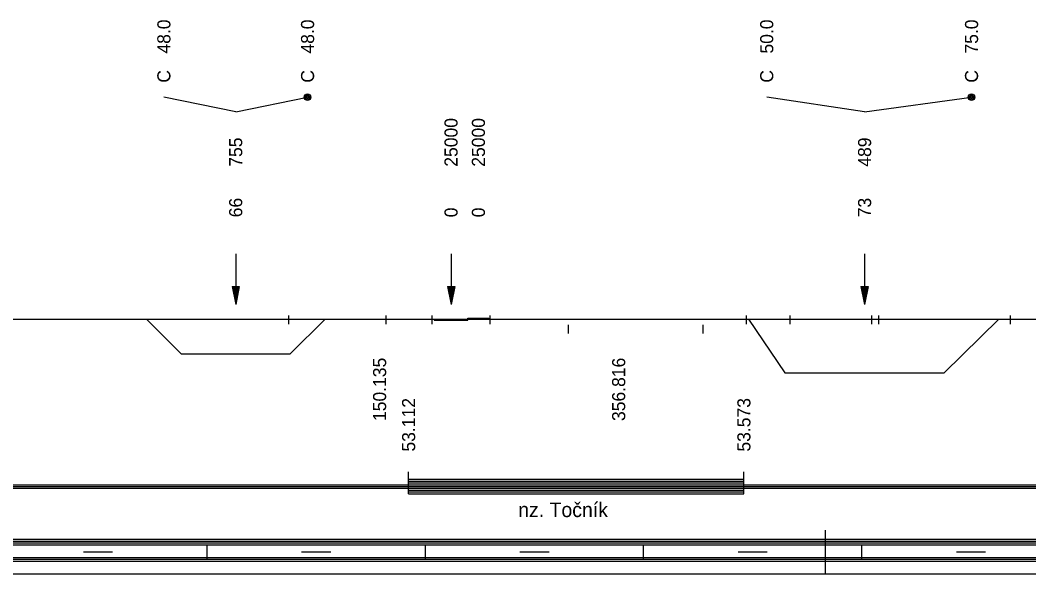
# Model space of a CAD drawing. Extents: x 2 to 10148, y 0 to 380.
# Drawn here: x 5559.3 to 5697.9, y 0 to 76.1 of the extents above; entities that cross this region are included whole.
import ezdxf

# ---------------------------------------------------------------- set-up
doc = ezdxf.new("R2010")
doc.units = 0
for name, color, linetype in [('KRIV1_CARA', 7, 'Continuous'), ('KRIV1_TEXT', 7, 'Continuous'), ('L_OBJEKTY_TEXT', 7, 'Continuous'), ('L_OBJEKTY_TVAR', 7, 'Continuous'), ('RAM', 7, 'Continuous'), ('STAN_CARA', 7, 'Continuous')]:
    doc.layers.add(name, color=color, linetype=linetype)

msp = doc.modelspace()

# ---------------------------------------------------------------- linework, layer by layer
for p, q in [((5596.19, 35.51), (5596.19, 34.32)), ((5609.58, 35.51), (5609.58, 34.32)), ((5615.9, 35.51), (5615.9, 34.32)), ((5623.88, 35.51), (5623.88, 34.32)), ((5659.08, 35.51), (5659.08, 34.32)), ((5665.09, 35.51), (5665.09, 34.32)), ((5676.33, 35.51), (5676.33, 34.32)), ((5677.27, 35.51), (5677.27, 34.32)), ((5695.36, 35.51), (5695.36, 34.32)), ((5634.63, 34.2), (5634.63, 33.01)), ((5653.13, 34.2), (5653.13, 33.01))]:
    msp.add_line(p, q)
at = {"layer": 'KRIV1_CARA'}
for p, q in [((5128.6, 35), (5974.91, 35)), ((5576.66, 35), (5581.46, 30.23)), ((5596.41, 30.23), (5601.21, 35)), ((5616.22, 35), (5616.22, 34.86)), ((5616.22, 34.86), (5620.85, 34.86)), ((5620.85, 35), (5620.85, 35.14)), ((5620.85, 35.14), (5623.73, 35.14)), ((5620.85, 34.86), (5620.85, 35)), ((5623.73, 35.14), (5623.73, 35)), ((5659.42, 35), (5664.42, 27.64)), ((5686.32, 27.64), (5693.82, 35)), ((5581.46, 30.23), (5596.41, 30.23)), ((5664.42, 27.64), (5686.32, 27.64))]:
    msp.add_line(p, q, dxfattribs=at)
at = {"layer": 'KRIV1_TEXT'}
for p, q in [((5588.93, 63.5), (5579.06, 65.5)), ((5588.93, 63.5), (5598.81, 65.5)), ((5675.37, 63.5), (5661.92, 65.5)), ((5675.37, 63.5), (5690.07, 65.5)), ((5588.93, 44), (5588.93, 42.2)), ((5618.53, 44), (5618.53, 42.2)), ((5675.37, 44), (5675.37, 42.2)), ((5588.93, 42.2), (5588.93, 40)), ((5618.53, 42.2), (5618.53, 40)), ((5675.37, 42.2), (5675.37, 40)), ((5588.43, 39.5), (5588.93, 37)), ((5588.43, 39.5), (5589.43, 39.5)), ((5588.53, 39.5), (5588.93, 37.5)), ((5588.63, 39.5), (5588.93, 38)), ((5588.73, 39.5), (5588.93, 38.5)), ((5588.83, 39.5), (5588.93, 39)), ((5588.93, 40), (5588.93, 37)), ((5589.43, 39.5), (5588.93, 37)), ((5589.33, 39.5), (5588.93, 37.5)), ((5589.23, 39.5), (5588.93, 38)), ((5589.13, 39.5), (5588.93, 38.5)), ((5589.03, 39.5), (5588.93, 39)), ((5588.93, 39.5), (5588.93, 39.5)), ((5588.93, 39.5), (5588.93, 39.5)), ((5618.03, 39.5), (5618.53, 37)), ((5618.03, 39.5), (5619.03, 39.5)), ((5618.13, 39.5), (5618.53, 37.5)), ((5618.23, 39.5), (5618.53, 38)), ((5618.33, 39.5), (5618.53, 38.5)), ((5618.43, 39.5), (5618.53, 39)), ((5618.53, 40), (5618.53, 37)), ((5619.03, 39.5), (5618.53, 37)), ((5618.93, 39.5), (5618.53, 37.5)), ((5618.83, 39.5), (5618.53, 38)), ((5618.73, 39.5), (5618.53, 38.5)), ((5618.63, 39.5), (5618.53, 39)), ((5618.53, 39.5), (5618.53, 39.5)), ((5618.53, 39.5), (5618.53, 39.5)), ((5674.87, 39.5), (5675.37, 37)), ((5674.87, 39.5), (5675.87, 39.5)), ((5674.97, 39.5), (5675.37, 37.5)), ((5675.07, 39.5), (5675.37, 38)), ((5675.17, 39.5), (5675.37, 38.5)), ((5675.27, 39.5), (5675.37, 39)), ((5675.37, 40), (5675.37, 37)), ((5675.87, 39.5), (5675.37, 37)), ((5675.77, 39.5), (5675.37, 37.5)), ((5675.67, 39.5), (5675.37, 38)), ((5675.57, 39.5), (5675.37, 38.5)), ((5675.47, 39.5), (5675.37, 39)), ((5675.37, 39.5), (5675.37, 39.5)), ((5675.37, 39.5), (5675.37, 39.5))]:
    msp.add_line(p, q, dxfattribs=at)
for centre, radius in [((5598.81, 65.5), 0.45), ((5598.81, 65.5), 0.3), ((5598.81, 65.5), 0.15), ((5690.07, 65.5), 0.45), ((5690.07, 65.5), 0.3), ((5690.07, 65.5), 0.15)]:
    msp.add_circle(centre, radius, dxfattribs=at)
at = {"layer": 'L_OBJEKTY_TVAR'}
for p, q in [((5612.7, 11), (5612.7, 14)), ((5658.78, 11), (5658.78, 14)), ((5612.7, 13), (5658.78, 13)), ((5612.7, 12.75), (5658.78, 12.75)), ((5612.7, 12.5), (5658.78, 12.5)), ((5612.7, 12.25), (5658.78, 12.25)), ((5612.7, 12), (5658.78, 12)), ((5612.7, 11.75), (5658.78, 11.75)), ((5612.7, 11.5), (5658.78, 11.5)), ((5612.7, 11.25), (5658.78, 11.25)), ((5612.7, 11), (5658.78, 11))]:
    msp.add_line(p, q, dxfattribs=at)
at = {"layer": 'RAM'}
for p, q in [((5670, 0), (5670, 6)), ((5128.6, 4.75), (5974.91, 4.75)), ((5128.6, 4.5), (5974.91, 4.5)), ((5128.6, 4.25), (5974.91, 4.25)), ((5128.6, 4), (5974.91, 4)), ((5568, 3), (5572, 3)), ((5585, 2), (5585, 4)), ((5598, 3), (5602, 3)), ((5615, 2), (5615, 4)), ((5628, 3), (5632, 3)), ((5645, 2), (5645, 4)), ((5658, 3), (5662, 3)), ((5675, 2), (5675, 4)), ((5688, 3), (5692, 3)), ((5128.6, 2.25), (5974.91, 2.25)), ((5128.6, 2), (5974.91, 2)), ((5128.6, 1.75), (5974.91, 1.75)), ((5128.6, 0), (5974.91, 0))]:
    msp.add_line(p, q, dxfattribs=at)
at = {"layer": 'STAN_CARA'}
for p, q in [((5302.99, 12.25), (5799.99, 12.25)), ((5302.99, 12), (5799.99, 12)), ((5302.99, 12), (5799.99, 12)), ((5302.99, 11.75), (5799.99, 11.75))]:
    msp.add_line(p, q, dxfattribs=at)

# ---------------------------------------------------------------- texts
at = {"layer": 'KRIV1_TEXT'}
for s, p in [('48.0', (5579.96, 71.5)), ('48.0', (5599.71, 71.5)), ('50.0', (5662.82, 71.5)), ('75.0', (5690.97, 71.5)), ('C', (5579.96, 67.5)), ('C', (5599.71, 67.5)), ('C', (5662.82, 67.5)), ('C', (5690.97, 67.5)), ('25000', (5619.43, 55.95)), ('25000', (5623.19, 55.95)), ('755', (5589.83, 55.95)), ('489', (5676.27, 55.95)), ('66', (5589.83, 49)), ('73', (5676.27, 49)), ('0', (5619.43, 49)), ('0', (5623.19, 49)), ('150.135', (5609.61, 21)), ('356.816', (5642.47, 21))]:
    msp.add_text(s, height=1.8, rotation=90, dxfattribs=at).set_placement(p)
at = {"layer": 'L_OBJEKTY_TEXT'}
for s, p in [('53.112', (5613.6, 16.8)), ('53.573', (5659.68, 16.8))]:
    msp.add_text(s, height=1.8, rotation=90, dxfattribs=at).set_placement(p)
msp.add_text('nz. Točník', height=2, dxfattribs=at).set_placement((5627.76, 7.8))

doc.saveas('drawing.dxf')
